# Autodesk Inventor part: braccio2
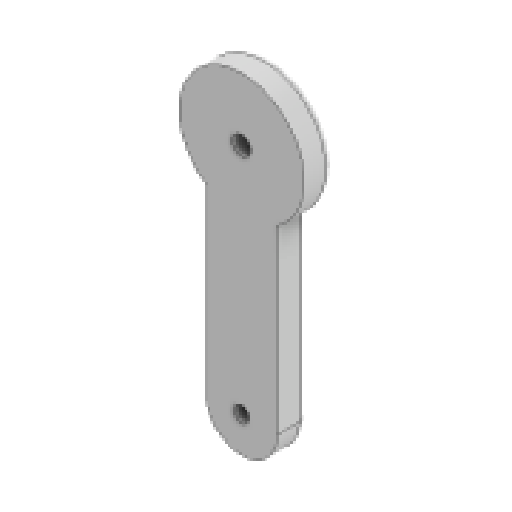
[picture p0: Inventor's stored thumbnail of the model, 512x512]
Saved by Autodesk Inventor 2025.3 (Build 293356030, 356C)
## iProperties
Created: 2025-09
Part Number: braccio2
Material: Generico
Document SubType Name: Modeling
Designer: Ryzen5700u
Density: 1 g/cm^3
Appearance: Default
Author: Ryzen5700u
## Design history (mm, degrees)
node "Piano di lavoro1"
sketch "Schizzo1" dims "d12" = 35
  geometry: L1 (-7, 0.5)-(7, 0.5) reference; L2 (17.956, -46.319)-(17.956, -121.319); L3 (27.956, -60.68)-(7.956, -60.68); L4 (7.956, -60.68)-(7.956, -121.319); L5 (7.956, -121.319)-(27.956, -121.319); L6 (27.956, -121.319)-(27.956, -60.68); L7 (-7, -39.753)-(-7, 0.5) reference; L8 (7, 0.5)-(7, -39.753) reference; C1 r 2.25 at (0, -49.5) reference; A1 r 12 centre (0, -49.5) between (-7, -39.753) and (7, -39.753) reference; 1 further point
  constraints: 10 end point, 2 parallel, 1 horizontal, 1 perpendicular, 1 vertical, 4 other
  dimensions: "d3" = 20 distance of L5.end L4.end; "d27" = 75 distance from line of L5 L2.start
extrude "Estrusione1" new body sketch "Schizzo1" distance "d0" = 8; taper "d1" = 0 deg
sketch "Schizzo2"
  geometry: C1 r 2.25 at (-17.956, -114.5) reference; 1 further point
hole "Foro1" sketch "Schizzo2" at (-17.956, -114.5) diameter "d5" = 4.5; stored, may be unused: countersink angle "d9" = 90 deg, drill point angle "d11" = 118 deg; dims "d6" = 6, "d7" = 8, "d8" = 4.6, "d10" = 8
sketch "Schizzo3"
  geometry: A1 r 17.5 centre (-17.956, -46.319) between (-7.956, -60.68) and (-27.956, -60.68) reference; 2 further points
  constraints: 1 coincident
hole "Foro2" sketch "Schizzo3" at (-17.956, -46.319) diameter "d13" = 5.3; stored, may be unused: countersink angle "d17" = 90 deg, drill point angle "d19" = 118 deg; dims "d14" = 6, "d15" = 8, "d16" = 4.6, "d18" = 8
sketch "Schizzo6"
  geometry: L1 (-14.478, -67.818)-(-14.478, -99.791); L2 (-14.478, -99.791)-(-19.673, -99.791); L3 (-19.673, -99.791)-(-19.673, -67.818); L4 (-19.673, -67.818)-(-14.478, -67.818); 1 further point
  constraints: 2 other
extrude "Estrusione3" cut sketch "Schizzo6" distance "d23" = 0.2; taper "d24" = 0 deg
fillet "Raccordo3" dims "d25" = 10
fillet "Raccordo4" dims "d26" = 2
sketch "Schizzo7"
  geometry: A1 r 10 centre (17.956, -111.319) between (7.956, -111.319) and (27.956, -111.319) reference; 2 further points
  constraints: 1 coincident
hole "Foro3" sketch "Schizzo7" at (17.956, -111.319) diameter "d28" = 4.3; stored, may be unused: countersink angle "d32" = 90 deg, drill point angle "d34" = 118 deg; dims "d29" = 6, "d30" = 8, "d31" = 4.6, "d33" = 8
sketch "Schizzo8"
  geometry: C1 r 2.15 at (-17.956, -111.319) reference; 2 further points
  constraints: 1 coincident
hole "Foro4" sketch "Schizzo8" at (-17.956, -111.319) diameter "d35" = 4.3; stored, may be unused: countersink angle "d39" = 90 deg, drill point angle "d41" = 118 deg; dims "d36" = 6, "d37" = 8, "d38" = 4, "d40" = 8
node "Solido1"
node "Riferimento1"
node "Riferimento2"
